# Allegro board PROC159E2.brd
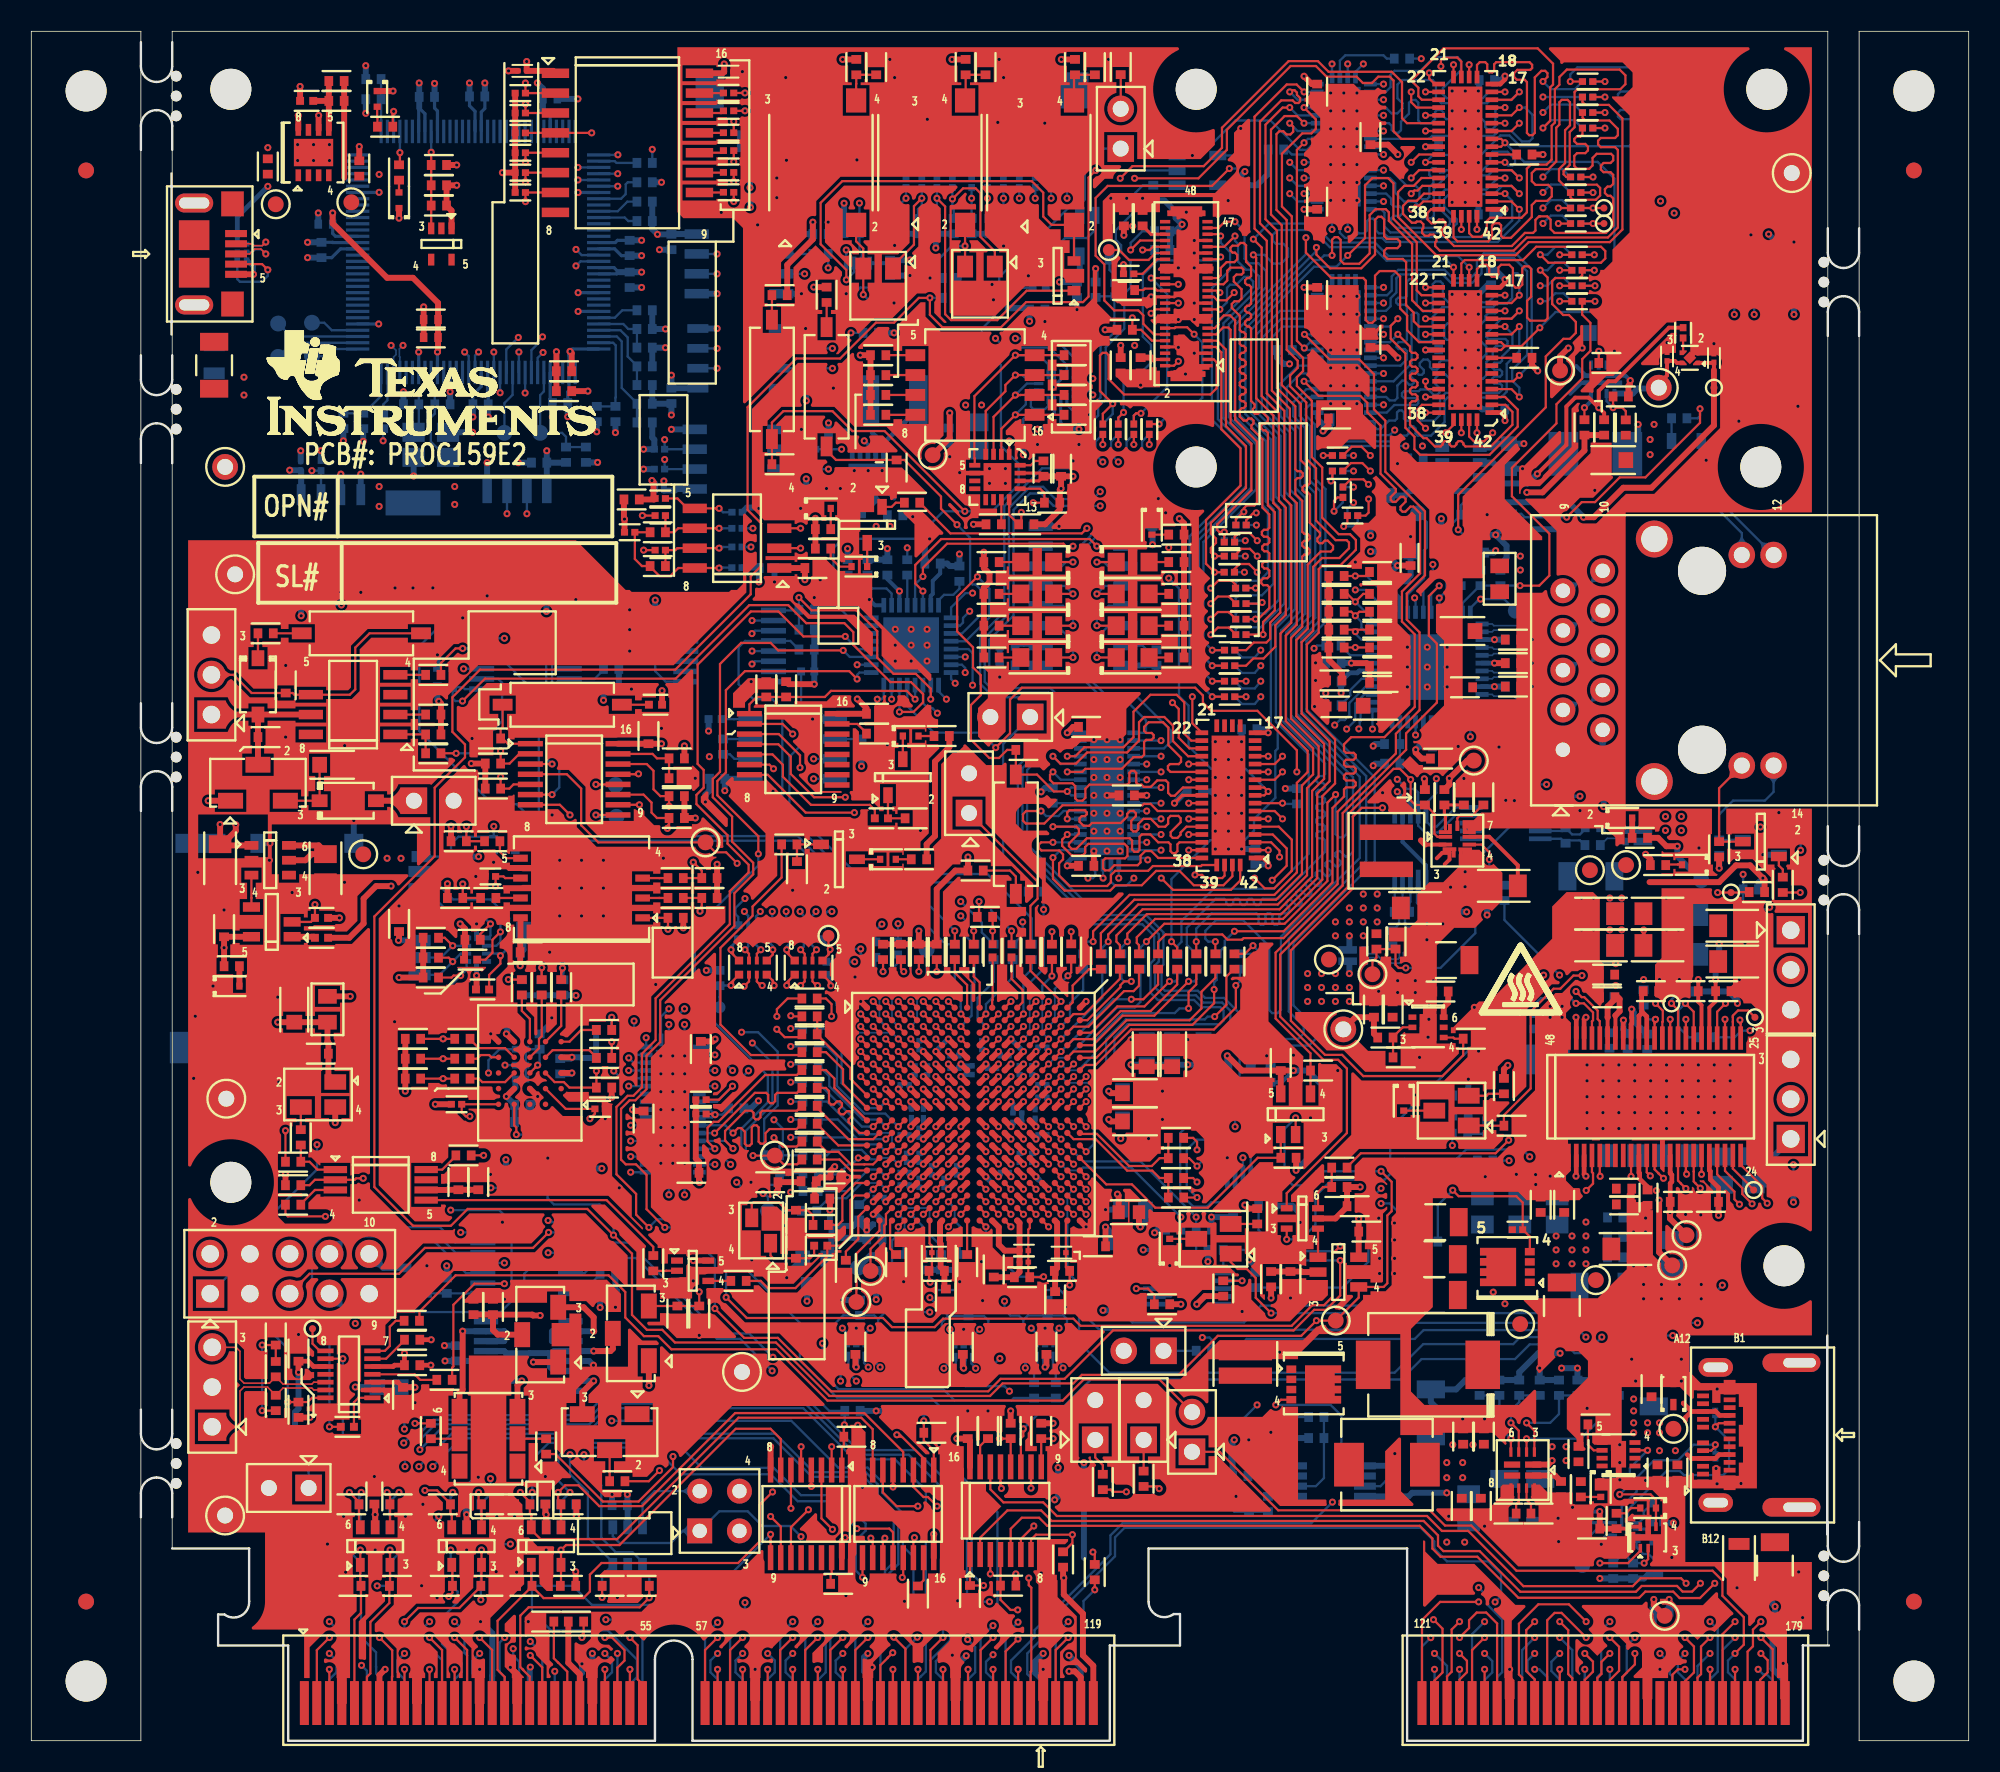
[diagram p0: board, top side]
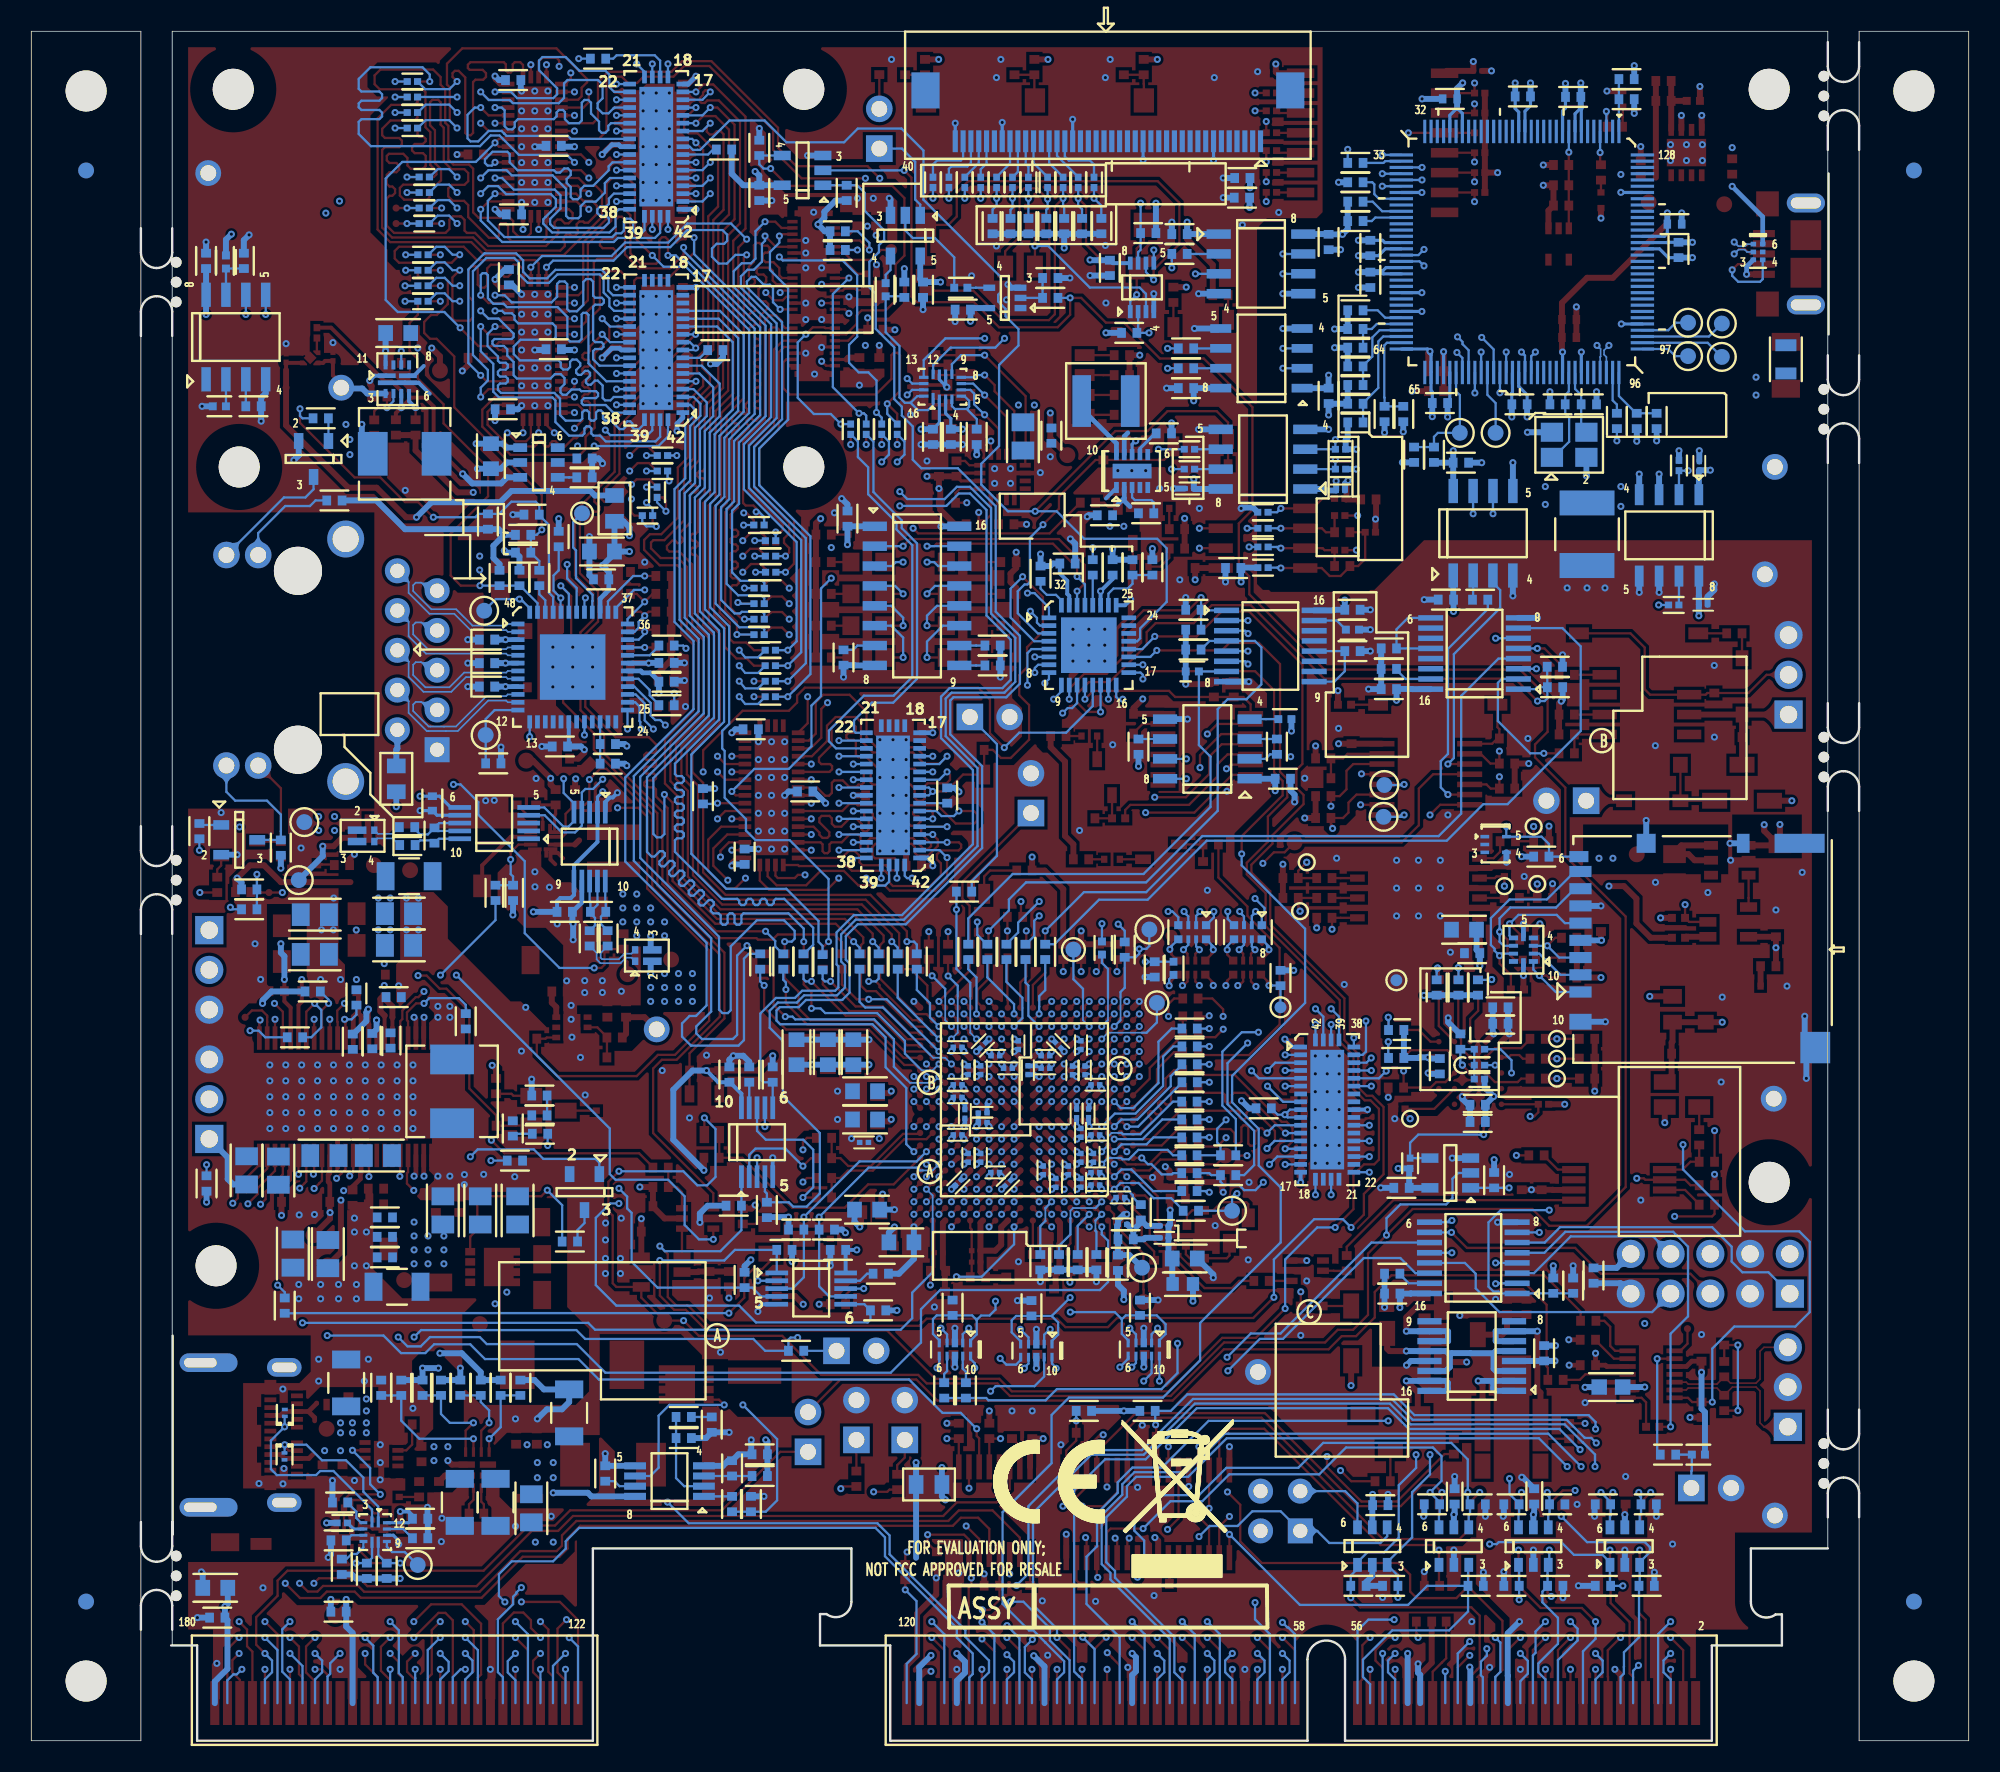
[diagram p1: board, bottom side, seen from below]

Outline 123.76 x 109.21 mm; copper layers: TOP, L02_GND1, L03_SIG1, L04_GND2, L05_PWR1, L06_PWR2, L07_GND3, L08_SIG2, L09_GND4, BOTTOM. Coordinates in mm from the lower left corner of the outline.
Outline path: 0,109.21 0,0 7,0 7,109.21 0,109.21 ; 9,109.21 114.76,109.21 114.76,6.09 113.17,6.09 113.17,0 87.89,0 87.89,12.28 71.37,12.28 71.37,8.88 arc(71.92,7.99) 72.97,8.09 73.38,8.09 73.38,6.08 68.89,6.08 68.89,0 42.24,0 42.24,5.2 arc(41.04,6.4) 39.84,5.2 39.84,0 16.41,0 16.41,6.08 11.93,6.08 11.93,8.06 12.34,8.06 arc(13.38,8.01) 13.91,8.9 13.91,12.28 9,12.28 9,109.21 ; 116.76,109.21 116.76,0 123.76,0 123.76,109.21 116.76,109.21

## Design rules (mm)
net group DIFFPAIR4: nets XDS_USB_D_N XDS_USB_D_P
net group DP1: nets MCAN4_CAN_H MCAN4_CAN_L
net group ICSSM_MI1_TX: nets ICSSM_MII1_TXCLK N35821153
net group ICSSM_MII0/MII1_RXCLK_ON: nets ICSSM_MII0/MII1_RXCLK_ON N34780998
net group ICSSM_MII0/MII1_RXER_ON: nets ICSSM_MII0/MII1_RXER_ON N34780980
net group ICSSM_MII0/MII1_TXCLK_ON: nets ICSSM_MII0/MII1_TXCLK_ON N34780978
net group MMC0_CLK: nets MMC0_CLK MMC0_CLK_R
net group OSPI_CS0: nets OSPI_CS0 SOC_OSPI0_CSN0
net group OSPI_DQ0: nets N35248046 OSPI_DQ0
net group OSPI_DQ1: nets N35244293 OSPI_DQ1
net group OSPI_DQ2: nets N35244332 OSPI_DQ2
net group OSPI_DQ3: nets N35244360 OSPI_DQ3
net group OSPI_DQ4: nets N35244387 OSPI_DQ4
net group OSPI_DQ5: nets N35244414 OSPI_DQ5
net group OSPI_DQ6: nets N35244441 OSPI_DQ6
net group OSPI_DQ7: nets N35244468 OSPI_DQ7
net group QSPI_CS1: nets QSPI_CS1 SOC_OSPI0_CSN1
net group QSPI_D0: nets N35230144 QSPI_D0
net group QSPI_D1: nets N35230147 QSPI_D1
net group QSPI_D2: nets N35252647 QSPI_D2
net group QSPI_D3: nets N35230153 QSPI_D3
net group SOC_OSPI0_CLK: nets N34603356 SOC_OSPI0_CLK
net group SOC_OSPI0_D0: nets N34603287 SOC_OSPI0_D0
net group SOC_OSPI0_D1: nets N34603290 SOC_OSPI0_D1
net group SOC_OSPI0_D2: nets N34603584 SOC_OSPI0_D2
net group SOC_OSPI0_D3: nets N34603591 SOC_OSPI0_D3
net group SOC_OSPI0_D4: nets N34800889 SOC_OSPI0_D4
net group SOC_OSPI0_D5: nets N34800892 SOC_OSPI0_D5
net group SOC_OSPI0_D6: nets N34800895 SOC_OSPI0_D6
net group SOC_OSPI0_D7: nets N34603328 SOC_OSPI0_D7
net group SOC_OSPI0_DQS: nets N35329989 SOC_OSPI0_DQS
net group SOC_OSPI0_LBCLK: nets N35329968 SOC_OSPI0_LBCLK
net group HSEC_ADC: nets ADC_CAL0 ADC_CAL0/ADC_R0_AIN0 ADC_CAL1 ADC_CAL1/ADC_R0_AIN1 ADC_CAL2 ADC_CAL3 ADC_R0_AIN0 ADC_R0_AIN1 ADC_R0_AIN2 ADC_R0_AIN3 ADC_R1_AIN0 ADC_R1_AIN1 ADC_R1_AIN2 ADC_R1_AIN3 HSEC_ADC0_AIN0 HSEC_ADC0_AIN0/DAC_OUT HSEC_ADC0_AIN1 HSEC_ADC0_AIN1/DAC_OUT HSEC_ADC0_AIN2 HSEC_ADC0_AIN3 HSEC_ADC0_AIN4 HSEC_ADC0_AIN5 HSEC_ADC1_AIN0 HSEC_ADC1_AIN1 HSEC_ADC1_AIN2 HSEC_ADC1_AIN3 HSEC_ADC1_AIN4 HSEC_ADC1_AIN5 HSEC_ADC2_AIN0 HSEC_ADC2_AIN1 HSEC_ADC2_AIN2 HSEC_ADC2_AIN3 HSEC_ADC3_AIN0 HSEC_ADC3_AIN1 HSEC_ADC3_AIN2 HSEC_ADC3_AIN3 HSEC_ADC3_AIN4 HSEC_ADC3_AIN5 HSEC_ADC4_AIN0 HSEC_ADC4_AIN1
net group N34755833: nets N34869775
net group OPSI_DQS: nets OSPI_DQS_SOC
net group POWER: nets HSEC_VREF_3V3 VBAT_LIN VBAT_XDS VBUS_DET VCC_1V1 VCC_1V2_N VCC_1V2_P VDD_IO_3V3_N VDD_IO_3V3_P VDDC_1V2_XDS VLIN VMAIN_MON VREG VSYS_MON
net group VMAIN_12V0: nets N35537520

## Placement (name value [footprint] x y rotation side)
C1  0.1uF  [CAP0402_0-75]  98.92 14.18 180 bottom
C2  0.1uF  [CAP0402_0-75]  99.7 13.55 180 top
C3  0.1uF  [CAP0402_0-75]  105.15 17.13 270 top
C4  10uF  [CAP1206_2]  103.65 22.86 90 bottom
C5  0.1uF  [CAP0402_0-75]  103.5 22.47 90 top
C6  1000pF  [CAP1206_1-75]  111.38 11.18 90 top
C7  1uF  [CAP0402_0-75]  98.83 18.31 90 top
C8  1uF  [CAP0402_0-75]  103.88 17.13 270 top
C9  1000pF  [CAP0402_0-75]  99.92 20.21 0 top
C10  10uF  [CAP1206_2]  94.1 15.23 270 bottom
C11  1uF  [CAP0402_0-75]  92.6 15 270 top
C12  0.1uF  [CAP0402_0-75]  97.72 16.07 90 top
C13  10uF  [CAP1206_2]  89.4 20.94 90 bottom
C14  1uF  [CAP0402_0-75]  92.79 19.43 90 top
C15  0.1uF  [CAP0402_0-75]  91.47 19.43 90 top
C16  1uF  [CAP0402_0-75]  96.29 14.51 0 top
C17  47uF  [CAP1206_2]  96.39 15.23 270 bottom
C18  22uF  [CAP0805_1-5]  91.82 14.85 270 bottom
C19  0.1uF  [CAP0402_0-75]  91.38 15 270 top
C20  0.1uF  [CAP0402_0-75]  77.23 18.3 0 bottom
C21  47uF  [CAP1206_2]  89.69 33.13 180 top
C22  4700pF  [CAP0402_0-75]  82.08 19.33 180 bottom
C23  0.1uF  [CAP0402_0-75]  82.08 20.68 180 bottom
C24  10pF  [CAP0402_0-75]  77.79 15.12 90 bottom
C30  1000pF  [CAP0402_0-75]  100.65 48.94 180 top
C31  0.1uF  [CAP0402_0-75]  100.67 47.49 180 top
C32  22uF  [CAP0805_1-5]  100.27 52.84 180 bottom
C33  22uF  [CAP0805_1-5]  100.27 50.81 180 top
C34  22uF  [CAP0805_1-5]  100.27 50.81 180 bottom
C35  22uF  [CAP0805_1-5]  100.27 52.84 180 top
C36  0.1uF  [CAP0402_0-75]  100.61 47.5 180 bottom
C37  0.1uF  [CAP0402_0-75]  100.81 44.73 270 bottom
C38  220uF  [CAP1206_2]  99.63 55.23 180 bottom
C43  220uF  [CAP1206_2]  100.4 29 0 bottom
C44  10uF  [CAP0805_1-5]  97.47 33.88 90 bottom
C45  10uF  [CAP0805_1-5]  101.83 31.41 0 top
C46  10uF  [CAP0805_1-5]  95.08 33.88 90 bottom
C47  10uF  [CAP0805_1-5]  92.7 33.88 90 bottom
C48  2.2uF  [CAP0402_0-75]  97.92 34.24 90 top
C49  2.2uF  [CAP0402_0-75]  101.17 30.88 0 bottom
C50  1000pF  [CAP0402_0-75]  101.17 32.19 0 bottom
C51  1000pF  [CAP0402_0-75]  101.74 34.26 0 top
C52  0.1uF  [CAP0402_0-75]  96.42 34.24 90 top
C53  0.1uF  [CAP0402_0-75]  101.17 33.43 0 bottom
C54  0.1uF  [CAP0402_0-75]  101.74 35.27 0 top
C55  0.1uF  [CAP0402_0-75]  91.26 38.78 180 bottom
C56  0.1uF  [CAP0402_0-75]  96.01 45.96 90 bottom
C57  0.01uF  [CAP0402_0-75]  91.3 41.22 0 bottom
C58  10uF  [CAP0805_1-5]  103.88 52.84 0 top
C59  10uF  [CAP0805_1-5]  103.88 50.81 0 top
C60  0.1uF  [CAP0402_0-75]  103.46 47.89 0 top
C61  2.2uF  [CAP0402_0-75]  103.22 44.66 270 bottom
C62  4.7uF  [CAP0402_0-75]  101.98 44.69 270 bottom
C64  10uF  [CAP0805_1-5]  105.04 37.38 0 bottom
C65  10uF  [CAP0805_1-5]  101.62 37.38 180 bottom
C66  0.1uF  [CAP0402_0-75]  103.24 34.69 270 top
C67  10uF  [CAP0805_1-5]  107.05 31.12 270 bottom
C68  10uF  [CAP0805_1-5]  104.82 31.09 270 bottom
C69  0.1uF  [CAP0402_0-75]  105.18 34.42 0 top
C70  10uF  [CAP0805_1-5]  105.65 52.77 180 bottom
C71  10uF  [CAP0805_1-5]  105.65 50.23 180 bottom
C72  0.1uF  [CAP0402_0-75]  105.99 47.89 180 top
C73  0.1uF  [CAP0402_0-75]  59.82 19.79 90 top
C74  10uF  [CAP0805_1-5]  110.01 36.44 90 bottom
C75  10uF  [CAP0805_1-5]  107.98 36.42 90 bottom
C76  0.1uF  [CAP0402_0-75]  107.29 34.42 180 top
C77  10uF  [CAP0805_1-5]  108.65 49.78 0 top
C78  10uF  [CAP0805_1-5]  108.65 52.06 0 top
C79  0.1uF  [CAP0402_0-75]  108.08 47.89 0 top
C80  10uF  [CAP0805_1-5]  94.06 54.61 180 top
C81  22uF  [CAP0805_1-5]  88.39 53.2 0 top
C82  6800pF  [CAP0402_0-75]  92.76 60.27 90 top
C83  2.2uF  [CAP0402_0-75]  55.18 78.29 0 bottom
C84  22uF  [CAP0805_1-5]  60.42 83.33 270 bottom
C85  0.1uF  [CAP0402_0-75]  58.6 83.37 270 bottom
C86  0.1uF  [CAP0402_0-75]  53.84 65.61 0 top
C89  0.1uF  [CAP0402_0-75]  89.69 52.95 180 bottom
C90  0.1uF  [CAP0402_0-75]  98.14 59.88 270 bottom
C91  0.1uF  [CAP0402_0-75]  87.55 52.95 0 bottom
C92  0.1uF  [CAP0402_0-75]  98.01 57.83 90 bottom
C93  10uF  [CAP0603_1]  100.33 89.93 0 bottom
C94  22uF  [CAP0603_1]  101.05 81.81 180 top
C95  0.01uF  [CAP0402_0-75]  100.62 88.02 0 top
C96  1uF  [CAP0201_0-5]  104.49 88.43 90 top
C97  1uF  [CAP0201_0-5]  107.49 88.34 90 top
C98  10uF  [CAP0603_1]  94.4 82.06 270 bottom
C99  0.01uF  [CAP0402_0-75]  88.42 80.71 180 bottom
C100  1uF  [CAP0402_0-75]  88.42 81.92 180 bottom
C101  0.1uF  [CAP0201_0-5]  51.33 35.98 0 top
C102  3.3uF  [CAP0603_1]  74.88 43.99 90 bottom
C103  3.3uF  [CAP0603_1]  72.88 43.99 90 bottom
C104  3.3uF  [CAP0603_1]  68.18 31.84 180 bottom
C105  0.1uF  [CAP0201_0-5]  64.59 44.31 180 bottom
C106  0.1uF  [CAP0201_0-5]  56.7 44.44 270 bottom
C107  0.1uF  [CAP0201_0-5]  55.79 38.71 0 bottom
C108  0.1uF  [CAP0402_0-75]  68.13 31.59 180 top
C109  0.1uF  [CAP0201_0-5]  54.19 34.71 180 bottom
C110  0.1uF  [CAP0201_0-5]  58.97 43.75 180 bottom
C111  0.1uF  [CAP0201_0-5]  60.1 42.84 270 bottom
C112  0.1uF  [CAP0201_0-5]  64.12 40.04 90 bottom
C113  0.1uF  [CAP0201_0-5]  63.9 37.24 90 bottom
C114  0.1uF  [CAP0201_0-5]  62.99 39.51 180 bottom
C115  0.1uF  [CAP0201_0-5]  63.1 42.84 90 bottom
C116  0.1uF  [CAP0201_0-5]  63.1 37.24 90 bottom
C117  0.1uF  [CAP0201_0-5]  55.9 37.24 90 bottom
C118  0.1uF  [CAP0201_0-5]  60.7 44.44 270 bottom
C119  3.3uF  [CAP0603_1]  71.25 43.99 90 bottom
C120  3.3uF  [CAP0603_1]  71.25 43.86 90 top
C121  3.3uF  [CAP0603_1]  72.88 43.86 90 top
C122  0.1uF  [CAP0201_0-5]  56.99 40.07 90 bottom
C123  0.1uF  [CAP0201_0-5]  62.99 40.11 180 bottom
C124  0.1uF  [CAP0201_0-5]  64.59 41.11 180 bottom
C125  0.1uF  [CAP0201_0-5]  57.26 42.82 90 bottom
C126  0.1uF  [CAP0201_0-5]  58.97 42.95 180 bottom
C127  0.1uF  [CAP0201_0-5]  62.17 43.75 0 bottom
C128  0.1uF  [CAP0201_0-5]  56.46 42.82 90 bottom
C129  0.1uF  [CAP0201_0-5]  56.22 40.08 90 bottom
C130  0.1uF  [CAP0201_0-5]  56.7 37.24 90 bottom
C131  0.1uF  [CAP0201_0-5]  56.7 38.84 270 bottom
C132  0.1uF  [CAP0201_0-5]  63.9 42.84 90 bottom
C133  0.1uF  [CAP0201_0-5]  61.37 42.95 180 bottom
C134  3.3uF  [CAP0603_1]  70.37 33.93 180 bottom
C135  0.1uF  [CAP0201_0-5]  59.1 36.44 90 bottom
C136  0.1uF  [CAP0201_0-5]  62.19 36.31 0 bottom
C137  0.1uF  [CAP0201_0-5]  57.5 36.44 90 bottom
C138  3.3uF  [CAP0603_1]  70.5 39.69 0 bottom
C139  0.1uF  [CAP0201_0-5]  64.54 35.66 135 bottom
C140  4.7uF  [CAP0603_1]  50.08 30.8 180 bottom
C141  0.1uF  [CAP0201_0-5]  51.39 32.13 0 bottom
C142  0.1uF  [CAP0201_0-5]  51.39 32.89 0 bottom
C143  0.1uF  [CAP0201_0-5]  56.7 35.64 90 bottom
C144  0.1uF  [CAP0201_0-5]  61.38 35.62 135 bottom
C145  0.1uF  [CAP0201_0-5]  58.3 35.64 90 bottom
C146  0.1uF  [CAP0201_0-5]  55.79 35.51 0 bottom
C147  3.3uF  [CAP0603_1]  70.5 41.49 0 bottom
C148  3.3uF  [CAP0603_1]  70.5 41.37 0 top
C149  3.3uF  [CAP0603_1]  70.5 39.56 0 top
C150  0.1uF  [CAP0201_0-5]  55.79 36.31 0 bottom
C151  0.1uF  [CAP0201_0-5]  70.56 38.22 0 bottom
C152  0.1uF  [CAP0201_0-5]  58.17 44.43 225 bottom
C153  0.1uF  [CAP0201_0-5]  64.59 38.71 180 bottom
C154  0.1uF  [CAP0201_0-5]  55.79 41.91 0 bottom
C155  0.1uF  [CAP0201_0-5]  64.59 41.91 180 bottom
C156  0.1uF  [CAP0201_0-5]  62.98 44.42 315 bottom
C157  0.1uF  [CAP0402_0-75]  31.72 50.37 0 top
C158  0.1uF  [CAP0402_0-75]  31.72 50.31 0 bottom
C159  4.7uF  [CAP0603_1]  32.24 51.81 180 bottom
C160  0.1uF  [CAP0402_0-75]  29.92 46.85 180 bottom
C161  0.1uF  [CAP0402_0-75]  33.78 43.09 270 bottom
C162  0.1uF  [CAP0402_0-75]  31.36 40.63 0 bottom
C163  0.1uF  [CAP0402_0-75]  29.92 45.8 180 bottom
C164  4.7uF  [CAP0402_0-75]  31.36 39.53 180 bottom
C166  0.1uF  [CAP0402_0-75]  36.23 35.32 0 bottom
C167  0.1uF  [CAP0402_0-75]  12.31 51.85 90 top
C168  22uF  [CAP0805_1-5]  12.06 56.38 270 top
C169  22uF  [CAP0805_1-5]  18.79 55.74 270 top
C170  0.1uF  [CAP0402_0-75]  23.49 52.18 90 top
C171  0.1uF  [CAP0402_0-75]  39.37 72.25 180 bottom
C172  0.1uF  [CAP0402_0-75]  43.81 61.46 0 bottom
C173  0.1uF  [CAP0402_0-75]  112.6 94.54 90 bottom
C174  0.1uF  [CAP0402_0-75]  23.74 22.09 90 top
C175  0.1uF  [CAP0402_0-75]  24.33 23.99 180 top
C176  4700pF  [CAP0402_0-75]  15.62 25.77 90 top
C177  0.1uF  [CAP0402_0-75]  39.42 64.18 90 top
C178  1uF  [CAP0402_0-75]  41.23 62.76 180 top
C179  0.1uF  [CAP0402_0-75]  33.4 72.9 180 bottom
C180  0.1uF  [CAP0402_0-75]  32.44 81.65 0 bottom
C181  0.1uF  [CAP0402_0-75]  50 86.41 180 bottom
C182  0.1uF  [CAP0402_0-75]  40.89 85.92 90 bottom
C183  10pF  [CAP1812_1-25]  24.38 77.08 90 bottom
C184  12pF  [CAP0402_0-75]  48.85 31.31 90 top
C185  12pF  [CAP0402_0-75]  48.85 33.4 270 top
C186  22pF  [CAP0201_0-5]  54.06 32.98 0 bottom
C187  0.1uF  [CAP0402_0-75]  23.97 29.72 90 bottom
C188  0.1uF  [CAP0402_0-75]  36.83 28.56 0 bottom
C189  0.1uF  [CAP0402_0-75]  79.81 43.3 90 top
C190  10uF  [CAP0603_1]  87.31 75.97 0 bottom
C191  1uF  [CAP0402_0-75]  85.97 67.59 0 top
C192  1uF  [CAP0402_0-75]  85.97 68.66 0 top
C193  1uF  [CAP0402_0-75]  83.18 68.86 180 bottom
C195  0.1uF  [CAP0402_0-75]  94.65 68.84 0 top
C196  0.1uF  [CAP0402_0-75]  87.36 74.19 0 bottom
C197  0.1uF  [CAP0402_0-75]  88.11 75.57 90 top
C199  0.01uF  [CAP0402_0-75]  94.65 68.84 0 bottom
C206  10uF  [CAP0603_1]  91.42 70.89 180 top
C207  1uF  [CAP0402_0-75]  94.65 67.34 0 bottom
C208  1uF  [CAP0402_0-75]  94.65 70.34 0 bottom
C209  0.1uF  [CAP0402_0-75]  94.65 67.34 0 top
C210  0.1uF  [CAP0402_0-75]  91.58 67.3 180 top
C211  0.01uF  [CAP0402_0-75]  94.65 70.34 0 top
C212  10uF  [CAP0603_1]  85.88 66.12 0 top
C213  1uF  [CAP0402_0-75]  83.27 66.07 180 top
C214  1uF  [CAP0402_0-75]  83.18 67.65 180 bottom
C216  0.1uF  [CAP0402_0-75]  90 63.52 0 bottom
C217  0.1uF  [CAP0402_0-75]  89.87 62.74 0 top
C219  0.01uF  [CAP0402_0-75]  83.24 67.74 180 top
C220  10uF  [CAP0402_0-75]  69.59 87.87 270 top
C221  0.1uF  [CAP0402_0-75]  70.86 87.87 270 top
C222  0.1uF  [CAP0402_0-75]  77.26 98.88 270 bottom
C225  10uF  [CAP0402_0-75]  70.99 97.27 90 top
C226  0.1uF  [CAP0402_0-75]  69.79 97.27 90 top
C230  10uF  [CAP0603_1]  16.8 46.7 90 top
C231  1uF  [CAP0402_0-75]  28.55 35.69 90 top
C232  0.1uF  [CAP0402_0-75]  27.28 35.69 90 top
C233  0.01uF  [CAP0402_0-75]  18.49 43.89 180 top
C234  0.1uF  [CAP0402_0-75]  37.04 67.18 0 bottom
C235  10uF  [CAP0603_1]  19.22 62.35 0 top
C236  0.1uF  [CAP0402_0-75]  14.97 64.12 0 top
C237  220pF  [CAP0402_0-75]  16.25 67.42 90 top
C238  0.1uF  [CAP0402_0-75]  46.43 98.58 0 bottom
C239  0.1uF  [CAP0402_0-75]  46.4 99.83 0 bottom
C240  0.1uF  [CAP0402_0-75]  49.91 74.92 0 top
C241  0.1uF  [CAP0402_0-75]  46.99 74.92 0 bottom
C242  0.1uF  [CAP0402_0-75]  65.02 83.3 270 bottom
C243  0.1uF  [CAP0402_0-75]  66.16 83.3 270 bottom
C244  0.1uF  [CAP0402_0-75]  65.78 81.27 90 top
C245  0.1uF  [CAP0402_0-75]  64.26 91.43 180 bottom
C246  0.1uF  [CAP0402_0-75]  66.8 92.7 90 bottom
C247  1000pF  [CAP0402_0-75]  58.67 93.45 180 bottom
C248  15pF  [CAP0402_0-75]  19.49 106.03 180 top
C249  1uF  [CAP0402_0-75]  20.95 100.44 90 top
C250  1uF  [CAP0402_0-75]  28.48 105.04 0 bottom
C251  0.1uF  [CAP0402_0-75]  25.27 105.02 0 bottom
C252  0.1uF  [CAP0402_0-75]  28.7 85.37 180 bottom
C253  0.01uF  [CAP0402_0-75]  38.22 95.36 270 bottom
C254  0.01uF  [CAP0402_0-75]  18.54 95.24 90 bottom
C255  0.01uF  [CAP0402_0-75]  33.78 85.46 0 bottom
C256  2.2uF  [CAP0402_0-75]  15.11 100.57 90 top
C257  1uF  [CAP0402_0-75]  38.22 93.33 270 bottom
C258  0.01uF  [CAP0402_0-75]  33.14 104.89 0 bottom
C259  2.2uF  [CAP0402_0-75]  25.52 89.65 180 top
C260  1uF  [CAP0402_0-75]  25.52 90.79 180 top
C261  0.01uF  [CAP0402_0-75]  18.79 96.89 180 bottom
C262  0.1uF  [CAP0402_0-75]  34.03 87.49 0 top
C263  1000pF  [CAP1206_1-75]  11.68 87.87 270 top
C264  0.1uF  [CAP0402_0-75]  21.2 84.32 270 bottom
C265  0.1uF  [CAP0402_0-75]  50.41 96.25 0 bottom
C266  0.1uF  [CAP0402_0-75]  40.89 95.75 270 bottom
C267  0.01uF  [CAP0402_0-75]  26.03 98.07 0 top
C268  0.1uF  [CAP0402_0-75]  26.03 99.37 0 top
C269  12pF  [CAP0402_0-75]  26.26 85.37 180 bottom
C270  12pF  [CAP0402_0-75]  24.26 85.37 0 bottom
C271  0.1uF  [CAP0201_0-5]  40.13 79.87 0 bottom
C272  0.1uF  [CAP0201_0-5]  49.78 80 180 bottom
C273  0.1uF  [CAP0201_0-5]  31.36 106.68 0 top
C274  0.1uF  [CAP0201_0-5]  17.21 81.45 90 bottom
C275  0.1uF  [CAP0201_0-5]  16.96 72.57 180 bottom
C276  0.1uF  [CAP0402_0-75]  71.62 78.07 90 bottom
C277  0.1uF  [CAP0402_0-75]  57.57 75.21 180 bottom
C278  0.1uF  [CAP0402_0-75]  54.69 74.96 90 bottom
C279  0.1uF  [CAP0402_0-75]  29.49 27.71 90 top
C280  4.7uF  [CAP0402_0-75]  28.25 27.71 90 top
C281  0.1uF  [CAP0402_0-75]  37.59 15.05 180 bottom
C282  0.1uF  [CAP0402_0-75]  27.76 15.61 90 bottom
C283  0.1uF  [CAP0402_0-75]  32.84 15.61 90 bottom
C284  0.1uF  [CAP0402_0-75]  27.12 24.75 90 bottom
C285  4.7uF  [CAP0402_0-75]  63.29 29.61 180 top
C286  0.1uF  [CAP0201_0-5]  63.41 30.58 180 top
C287  0.1uF  [CAP0201_0-5]  63.41 31.31 180 top
C288  4.7uF  [CAP0402_0-75]  57.84 30.01 0 top
C289  0.1uF  [CAP0201_0-5]  57.81 31.18 0 top
C290  330pF  [CAP0402_0-75]  20.57 9.89 180 top
C291  330pF  [CAP0402_0-75]  23.36 9.89 0 top
C292  330pF  [CAP0402_0-75]  23.36 15.1 0 bottom
C293  330pF  [CAP0402_0-75]  20.44 15.1 180 bottom
C294  330pF  [CAP0402_0-75]  26.28 15.1 180 top
C295  330pF  [CAP0402_0-75]  29.25 15.1 0 top
C296  330pF  [CAP0402_0-75]  23.36 9.89 0 bottom
C297  330pF  [CAP0402_0-75]  20.57 9.89 180 bottom
C298  330pF  [CAP0402_0-75]  26.41 9.89 180 top
C299  330pF  [CAP0402_0-75]  29.21 9.89 0 top
C300  330pF  [CAP0402_0-75]  29.21 15.1 0 bottom
C301  330pF  [CAP0402_0-75]  26.28 15.1 180 bottom
C302  330pF  [CAP0402_0-75]  29.21 9.89 0 bottom
C303  330pF  [CAP0402_0-75]  26.41 9.89 180 bottom
C304  330pF  [CAP0402_0-75]  38.98 9.89 180 top
C305  330pF  [CAP0402_0-75]  36.95 9.89 0 top
C306  330pF  [CAP0402_0-75]  23.41 15.1 0 top
C307  330pF  [CAP0402_0-75]  20.44 15.1 180 top
C308  330pF  [CAP0402_0-75]  38.98 9.89 180 bottom
C309  330pF  [CAP0402_0-75]  36.95 9.89 0 bottom
C314  0.1uF  [CAP0402_0-75]  21.92 15.61 90 top
C315  0.1uF  [CAP0402_0-75]  32.84 15.61 90 top
C316  0.1uF  [CAP0402_0-75]  59.5 25.17 270 top
C318  330pF  [CAP0402_0-75]  31.49 9.89 180 bottom
C319  330pF  [CAP0402_0-75]  34.29 15.1 0 bottom
C320  330pF  [CAP0402_0-75]  31.36 15.1 180 bottom
C321  330pF  [CAP0402_0-75]  31.49 9.89 180 top
C322  330pF  [CAP0402_0-75]  34.29 9.89 0 top
C323  330pF  [CAP0402_0-75]  31.36 15.1 180 top
C324  330pF  [CAP0402_0-75]  34.33 15.1 0 top
C329  0.1uF  [CAP0402_0-75]  64.85 25.17 90 top
C330  0.1uF  [CAP0402_0-75]  52.64 25.17 270 top
C331  0.1uF  [CAP0402_0-75]  41.27 27.28 270 top
C332  10uF  [CAP0603_1]  112.01 9.77 0 bottom
C333  0.1uF  [CAP0402_0-75]  111.88 7.86 0 bottom
C334  0.1uF  [CAP0402_0-75]  104.14 8.24 0 bottom
C335  0.1uF  [CAP0402_0-75]  54.86 94.09 270 bottom
C336  0.1uF  [CAP0402_0-75]  53.97 106.92 90 top
C337  0.1uF  [CAP0402_0-75]  60.96 106.92 90 top
C338  0.1uF  [CAP0402_0-75]  67.94 106.92 90 top
C340  0.1uF  [CAP0402_0-75]  84.54 34.15 0 top
C341  0.1uF  [CAP0402_0-75]  85.28 32.52 0 top
C344  10uF  [CAP1206_2]  90.37 49.87 180 top
C345  0.1uF  [CAP0402_0-75]  90.02 47.86 180 top
C346  2.2uF  [CAP0402_0-75]  85.77 46.71 90 top
C347  0.1uF  [CAP0402_0-75]  86.96 46.71 90 top
C348  0.1uF  [CAP0402_0-75]  17.07 24.74 270 top
C349  4.7uF  [CAP0402_0-75]  65.84 30.01 180 top
C350  0.1uF  [CAP0201_0-5]  65.81 31.18 180 top
C351  0.1uF  [CAP0201_0-5]  44.54 106.63 180 top
C352  0.1uF  [CAP0402_0-75]  38.35 79.3 0 top
C353  47uF  [CAP1206_2]  89.63 28.47 180 top
C354  47uF  [CAP1206_2]  89.63 30.76 180 top
C355  47uF  [CAP1206_2]  97.77 27.77 270 top
C356  0.1uF  [CAP0402_0-75]  72.23 31.36 0 bottom
C357  0.1uF  [CAP0402_0-75]  78.19 56.47 90 bottom
C358  0.1uF  [CAP0402_0-75]  77.8 64.62 180 bottom
C359  0.1uF  [CAP0402_0-75]  74.33 60.64 0 bottom
C360  0.1uF  [CAP0402_0-75]  67.39 55.89 0 top
C361  0.1uF  [CAP0402_0-75]  67.39 64.77 0 top
C362  0.1uF  [CAP0402_0-75]  69.98 60.39 180 top
C363  0.1uF  [CAP0402_0-75]  92.93 97.51 180 bottom
C364  0.1uF  [CAP0402_0-75]  92.98 106.09 180 bottom
C365  0.1uF  [CAP0402_0-75]  90.39 101.89 0 bottom
C366  0.1uF  [CAP0402_0-75]  93.64 85.06 180 bottom
C367  0.1uF  [CAP0402_0-75]  93.25 93.5 270 bottom
C368  0.1uF  [CAP0402_0-75]  90.39 88.9 0 bottom
C369  0.1uF  [CAP0402_0-75]  83.35 84.47 0 top
C370  0.1uF  [CAP0402_0-75]  82.14 92.36 270 top
C371  0.1uF  [CAP0402_0-75]  85.54 89.5 90 top
C372  0.1uF  [CAP0402_0-75]  82.14 98.33 90 top
C373  0.1uF  [CAP0402_0-75]  82.14 105.35 270 top
C374  0.1uF  [CAP0402_0-75]  85.54 102.45 90 top
C3743  0.1uF  [CAP0402_0-75]  42.16 36.28 180 top
C3744  0.1uF  [CAP0402_0-75]  42.77 44.19 270 top
C3745  0.1uF  [CAP0402_0-75]  39.11 39.74 270 top
C3746  0.1uF  [CAP0402_0-75]  79.17 42.56 90 bottom
D1  TPD1E01B04DPLT  [DIO_DFN0201_0-4]  107.58 18.16 270 bottom
D2  TPD1E01B04DPLT  [DIO_DFN0201_0-4]  107.56 20.94 90 bottom
D3  PESD5Z6.0  [DIO_SOD523F_0-7]  104.9 22.21 90 top
D4  B540C-13-F  [DIO_SMC]  89.21 24.02 180 top
D6  1N4148W-7-F  [DIO_SOD123_1-4]  14.48 67.36 270 top
D7  1N4148W-7-F  [DIO_SOD123_1-4]  20.22 60.05 0 top
FB1  120E  [EMIFIL_BLM18S_0603_0-7]  22.86 22.59 0 bottom
FL1  120E  [EMIFIL_BLM18R_0603_1]  70.11 33.76 0 top
FL2  120E  [EMIFIL_BLM18R_0603_1]  50.2 29.18 180 bottom
FL3  100E  [EMIFIL_BLM18R_0603]  100.44 61.45 90 bottom
FL4  100E  [EMIFIL_BLM18R_0603]  86.51 78.73 270 bottom
FL5  100E  [EMIFIL_BLM18R_0603]  93.8 74.23 270 top
FL6  100E  [EMIFIL_BLM18R_0603]  18.92 46.73 90 top
FL7  100E  [EMIFIL_BLM18R_0603]  66.42 16.37 180 bottom
J1  CON_USB-C_24_F  [CON_USBC24_2012670_S_R_S_3-9]  110.85 19.53 90 top
J2  HDR_1X3  [HDR_1X3_100_S_T]  112.39 51.78 90 top
J3  HDR_1X3  [HDR_1X3_100_S_T]  112.39 38.44 270 top
J4  CON_SDCARD10_DM3BT-DSF-PEJS  [CON_SD10_DM3BT-DSF-PEJS_S_R_S_2-4]  17 50.55 90 bottom
J5  HDR_1X3  [HDR_1X3_100_S_T]  11.55 20.05 270 top
J6  HDR_2X5  [HDR_2X5_61301021121_S_T_8-6]  11.43 28.56 0 top
J7  CON_RJ45-14_LPJG16314A4NL  [CON_RJ45-14_LPJG16314A4NL_S_R_T_13-6]  97.84 63.31 90 top
J8  CON_BTOB_2X24_M  [CON_BTOB2X24_DF40GB-48DP_P_S_S_1-3]  73.78 92.44 90 top
J9  HDR_2X1  [HDR_2X1_100_S_T]  24.44 60.05 180 top
J10  HDR_1X3  [HDR_1X3_100_S_T]  11.51 65.56 270 top
J11  CON_FLEX_40X1_FH12A-40S-0.5SH  [CON_FLEX40X1_FH12A_S_R_S]  54.99 105.76 0 bottom
J12  HDR_2X1  [HDR_2X1_100_S_T]  69.59 101.71 270 top
J13  CON_MUSB-B_5_F  [CON_USBB5_2013499-1_S_R_S_3]  10.57 94.98 270 top
J14  HDR_2X2  [HDR_2X2_5-146256-2_S_T_8-3]  42.7 13.4 0 top
J15  CON_EDGE_PCIE_180_M  [CON_EDGE180_HSEC8-180_FING_P_R_S]  64.74 2.4 0 top
J16  HDR_2X1  [HDR_2X1_100_S_T_10-8]  71.05 19.22 270 top
J17  HDR_2X1  [HDR_2X1_100_S_T_10-8]  63.81 65.4 0 top
J18  HDR_2X1  [HDR_2X1_100_S_T_10-8]  59.9 59.26 270 top
J19  HDR_2X1  [HDR_2X1_100_S_T_10-8]  67.96 19.22 270 top
J20  HDR_2X1  [HDR_2X1_100_S_T_10-8]  72.32 24.91 0 top
J21  HDR_2X1  [HDR_2X1_100_S_T_10-8]  17.71 16.15 0 top
J22  HDR_2X1  [HDR_2X1_100_S_T_10-8]  74.14 18.46 270 top
L1  4.7uH  [IND_IHLP2020CZ-01_210X210_SMD_3]  86.6 17.63 180 top
L3  2.2uH  [IND_IHLP2020B_230X215_SMD]  96.88 41.49 90 bottom
L4  1uH  [IND_XAL4020_170X170_SMD_3-1]  86.56 56.85 270 top
L5  10uH  [IND_74405042100_170X170_SMD_2]  55.11 85.59 0 bottom
L6  1uH  [IND_IHLP2020B_230X215_SMD]  99.91 82.21 0 bottom
LD1  150040RS73220  [LED_150040GS73220_40X20_SMD_0-4]  103.28 14.86 180 top
LD2  150040VS73220  [LED_150040GS73220_40X20_SMD_0-4]  100.26 16.07 270 top
LD3  150040VS73220  [LED_150040GS73220_40X20_SMD_0-4]  105.94 55.96 180 top
LD4  150040VS73220  [LED_150040GS73220_40X20_SMD_0-4]  52.9 75.01 180 top
LD5  150040VS73220  [LED_150040GS73220_40X20_SMD_0-4]  50.57 78.73 0 top
LD6  150040RS73220  [LED_150040GS73220_40X20_SMD_0-4]  56.17 64.19 0 top
LD7  150040VS73220  [LED_150040GS73220_40X20_SMD_0-4]  54.72 56.31 0 top
LD8  150040RS73220  [LED_150040GS73220_40X20_SMD_0-4]  87.67 40.75 270 top
LD9  150040VS73220  [LED_150040GS73220_40X20_SMD_0-4]  23.49 98.41 90 top
LD10  150040RS73220  [LED_150040GS73220_40X20_SMD_0-4]  22.09 104.89 270 top
LD11  150080VS75000  [LED_150080VS75000_80X50_SMD_0-8]  70.35 75.3 0 top
LD12  150080VS75000  [LED_150080VS75000_80X50_SMD_0-8]  70.35 73.27 0 top
LD13  150080VS75000  [LED_150080VS75000_80X50_SMD_0-8]  70.35 71.23 0 top
LD14  150080VS75000  [LED_150080VS75000_80X50_SMD_0-8]  70.35 69.2 0 top
LD15  150080VS75000  [LED_150080VS75000_80X50_SMD_0-8]  64.26 69.2 180 top
LD16  150080VS75000  [LED_150080VS75000_80X50_SMD_0-8]  64.26 71.23 180 top
LD17  150080VS75000  [LED_150080VS75000_80X50_SMD_0-8]  64.26 73.27 180 top
LD18  150080VS75000  [LED_150080VS75000_80X50_SMD_0-8]  64.26 75.3 180 top
LD19  150040RS73220  [LED_150040GS73220_40X20_SMD_0-4]  72.72 31.56 90 top
LD20  150040VS73220  [LED_150040GS73220_40X20_SMD_0-4]  101.76 58.95 0 top
LD21  150040VS73220  [LED_150040GS73220_40X20_SMD_0-4]  71.58 77.55 270 top
LD22  150040VS73220  [LED_150040GS73220_40X20_SMD_0-4]  12.79 48.21 0 top
NOREF  -  [unnamed]  8 17.71 270 top
NOREF#2  -  [unnamed#2]  3.5 105.4 270 top
NOREF#3  -  [unnamed#2]  74.41 81.37 90 top
NOREF#4  -  [unnamed#2]  12.75 35.67 0 top
NOREF#5  -  [unnamed]  8 105.07 270 top
NOREF#6  -  [#3]  -299.48 162.29 0 top
NOREF#7  -  [#3]  123.76 0 90 top
NOREF#8  -  [#3]  9 12.28 0 top
NOREF#9  -  [unnamed#2]  120.26 3.81 90 top
NOREF#10  -  [unnamed#2]  3.5 8.89 270 top
NOREF#11  -  [unnamed]  115.76 54.98 90 top
NOREF#12  -  [unnamed#2]  12.75 105.5 0 top
NOREF#13  -  [unnamed#2]  110.48 81.37 90 top
NOREF#14  -  [unnamed#2]  120.26 100.32 90 top
NOREF#15  -  [unnamed]  8 62.84 270 top
NOREF#16  -  [unnamed#2]  3.5 100.32 270 top
NOREF#17  -  [unnamed]  8 85.07 270 top
NOREF#18  -  [unnamed#2]  120.26 8.89 90 top
NOREF#19  -  [unnamed#2]  74.41 105.5 90 top
NOREF#20  -  [unnamed]  115.76 10.53 90 top
NOREF#21  -  [#3]  28.14 -22.95 0 top
NOREF#22  -  [#3]  0 0 0 top
NOREF#23  -  [#3]  -265.05 -180.61 0 top
NOREF#24  -  [unnamed]  115.76 93.18 90 top
NOREF#25  -  [unnamed#2]  120.26 105.4 90 top
NOREF#26  -  [#3]  17.6 -117.69 0 top
NOREF#27  -  [unnamed#2]  3.5 3.81 270 top
NOREF#28  -  [#3]  -336.75 -31.84 0 top
NOREF#29  -  [unnamed#2]  110.86 105.5 90 top
NOREF#30  -  [#3]  0 109.21 0 top
NOREF#31  -  [unnamed#2]  111.96 30.34 0 top
NOREF#32  -  [unnamed#2]  120.26 8.89 270 bottom
NOREF#33  -  [unnamed#2]  3.5 8.89 90 bottom
NOREF#34  -  [unnamed#2]  3.5 100.32 90 bottom
NOREF#35  -  [unnamed#2]  120.26 100.32 270 bottom
Q2  BSS138LT1G  [SOT23-123_1-2]  53.4 77.68 270 top
Q3  BSS138LT1G  [SOT23-123_1-2]  55.67 61.56 90 top
Q4  BSS138LT1G  [SOT23-123_1-2]  51.59 56.31 0 top
Q5  IRLML6401  [TO_SOT23-123]  90.72 40.25 90 top
Q6  BSS138LT1G  [SOT23-123_1-2]  105.73 81.88 270 bottom
Q7  BSS138LT1G  [SOT23-123_1-2]  110.48 57.44 180 top
Q8  BSS138LT1G  [SOT23-123_1-2]  110.48 57.55 180 bottom
Q9  IRLML6401  [TO_SOT23-123]  54.1 92.95 180 top
Q10  IRLML6401  [TO_SOT23-123]  60.6 93.08 180 top
Q11  IRLML6401  [TO_SOT23-123#2]  65.56 93.59 180 top
Q12  BSS138LT1G  [SOT23-123_1-2]  88.42 35.05 270 bottom
Q13  CSD25404Q3T  [VSON8_CSD173_130X130_1-1]  94.29 30.26 180 top
Q20  IRLML6401  [TO_SOT23-123]  75.52 32.06 90 top
R1  620E_1%  [RES0402_0-5]  101.27 14.04 90 top
R2  4.7K  [RES0402_0-5]  104.03 15.22 180 bottom
R3  4.7K_1%  [RES0402_0-5]  101.05 10.86 90 bottom
R4  4.7K_1%  [RES0402_0-5]  102.32 10.86 90 bottom
R5  909K_1%  [RES0201_0-5]  103.89 13.91 0 bottom
R6  200K_1%  [RES0402_0-5]  103.92 11.11 90 bottom
R7  10K  [RES0402_0-5]  104.13 12.8 0 bottom
R8  0E  [RES0402_0-5]  98.92 12.93 180 bottom
R9  0E  [RES0805_0-75]  109.09 11.67 90 top
R10  22.1K_1%  [RES0402_0-5]  100.13 22.55 270 bottom
R11  9.53K_1%  [RES0402_0-5]  98.77 22.55 270 bottom
R12  22.1K_1%  [RES0402_0-5]  95.05 22.55 270 bottom
R13  4.7K_1%  [RES0402_0-5]  93.78 22.55 270 bottom
R14  4.7K_1%  [RES0402_0-5]  101.41 22.55 90 bottom
R15  4.7K_1%  [RES0402_0-5]  97.59 22.55 90 bottom
R16  4.7K_1%  [RES0402_0-5]  96.36 22.55 90 bottom
R17  4.7K_1%  [RES0402_0-5]  92.52 22.55 90 bottom
R18  44.2K_1%  [RES0402_0-5]  94.36 14.51 180 top
R20  10K  [RES0201_0-5]  94.94 32.65 180 top
R21  8.45K_1%  [RES0402_0-5]  77.23 16.91 180 bottom
R22  100E_1%  [RES0402_0-5]  79 15.12 270 bottom
R23  26.1K_1%  [RES0402_0-5]  87.1 17.07 90 bottom
R24  1.58K_1%  [RES0402_0-5]  80.29 20.19 270 bottom
R26  1K_1%  [RES0402_0-5]  79 17.4 270 bottom
R27  0.007E_1%  [RES1206_W_0-75]  77.55 24.07 90 top
R28  0E  [RES0402_0-5]  93 39.11 90 bottom
R29  1K_1%  [RES0402_0-5]  91.3 39.95 180 bottom
R31  10K  [RES0402_0-5]  19.21 18.28 0 bottom
R32  0E  [RES0402_0-5]  106.92 44.94 180 bottom
R34  10K  [RES0402_0-5]  74.91 24.91 0 bottom
R36  0E  [RES0402_0-5]  112.57 35.6 270 bottom
R38  10K  [RES0402_0-5]  109.84 54.39 180 bottom
R39  10K  [RES0402_0-5]  102.99 47.49 270 bottom
R40  10K  [RES0402_0-5]  110.23 54.22 180 top
R41  10K  [RES0402_0-5]  105.79 47.87 180 bottom
R42  0E  [RES0402_0-5]  92.87 37.06 180 bottom
R43  10K  [RES0402_0-5]  62.4 9.91 180 top
R44  10K  [RES0402_0-5]  65.91 11.58 90 top
R45  10K  [RES0402_0-5]  64.51 19.79 270 top
R46  10K  [RES0402_0-5]  62.56 19.79 270 top
R47  1K_1%  [RES0402_0-5]  98.99 16.06 270 top
R48  220E  [RES0402_0-5]  103.92 55.94 0 top
R49  10K  [RES0402_0-5]  59.96 9.43 270 top
R50  10K  [RES0402_0-5]  61.11 19.79 90 top
R51  0E  [RES0402_0-5]  94.11 54.17 90 bottom
R52  100K  [RES0402_0-5]  90.27 60.27 270 top
R53  10K_1%  [RES0402_0-5]  85.93 51.07 270 top
R55  10K_1%  [RES0402_0-5]  87.15 51.07 270 top
R56  100K  [RES0402_0-5]  91.51 60.27 270 top
R57  0E  [RES0402_0-5]  52.55 78.42 180 bottom
R58  100K_1%  [RES0402_0-5]  51.41 83.52 180 bottom
R59  10K_1%  [RES0402_0-5]  89.02 60.27 270 top
R62  10K  [RES0402_0-5]  48.22 67.17 270 top
R63  0E  [RES0402_0-5]  47.2 35.68 180 top
R67  10K  [RES0402_0-5]  46.95 67.17 90 top
R68  10E_1%  [RES0402_0-5]  86.95 51.26 270 bottom
R69  10E_1%  [RES0402_0-5]  99.74 57.22 0 bottom
R70  10E_1%  [RES0402_0-5]  88.09 51.26 270 bottom
R71  10E_1%  [RES0402_0-5]  99.76 58.36 0 bottom
R72  220E  [RES0402_0-5]  50.58 77.4 0 top
R73  220E  [RES0402_0-5]  50.58 76.16 0 top
R74  0.01E_1%  [RES_FC4L16_0306-4_0-7]  102.6 57.81 270 bottom
R75  0.01E_1%  [RES_FC4L16_0306-4_0-7]  84.44 50.16 90 bottom
R76  0E  [RES0402_0-5]  56.26 79.09 0 top
R77  10K_1%  [RES0402_0-5]  101.85 83.89 270 top
R78  0E  [RES0402_0-5]  99.21 83.9 270 top
R79  4.7K  [RES0402_0-5]  101.53 85.88 0 top
R80  10K_1%  [RES0402_0-5]  100.47 83.9 90 top
R81  0E  [RES0201_0-5]  105.52 89.94 270 top
R82  0E  [RES0402_0-5]  58.11 30.57 270 bottom
R83  0E  [RES0402_0-5]  49.66 35.74 0 top
R84  4.7K  [RES0402_0-5]  43.32 55.11 180 top
R85  4.7K  [RES0402_0-5]  27.07 53.84 0 top
R86  10K  [RES0402_0-5]  41.16 52.57 180 top
R87  0E  [RES0402_0-5]  49.71 38.27 0 top
R89  100K  [RES0201_0-5]  29.33 55.21 180 top
R90  0E  [RES0402_0-5]  49.78 36.26 0 bottom
R91  0E  [RES0402_0-5]  49.78 37.4 0 bottom
R92  0E  [RES0402_0-5]  49.78 40.83 0 bottom
R93  0E  [RES0402_0-5]  49.78 35.12 0 bottom
R94  0E  [RES0402_0-5]  49.71 39.42 0 top
R95  0E  [RES0402_0-5]  49.71 41.7 0 top
R96  0E  [RES0402_0-5]  49.71 40.56 0 top
R97  0E  [RES0402_0-5]  49.71 42.84 0 top
R98  0E  [RES0402_0-5]  49.71 37.13 0 top
R99  0E  [RES0402_0-5]  49.69 33.85 0 bottom
R100  49.9K_1%  [RES0402_0-5]  32.59 48.12 270 bottom
R101  49.9K_1%  [RES0402_0-5]  36.57 43.62 180 bottom
R102  4.7K  [RES0402_0-5]  24.38 42.3 0 top
R103  49.9K_1%  [RES0402_0-5]  24.38 44.84 180 top
R104  49.9K_1%  [RES0402_0-5]  24.38 43.57 180 top
R105  49.9K_1%  [RES0402_0-5]  31.35 48.12 270 bottom
R106  49.9K_1%  [RES0402_0-5]  33.99 48.12 270 bottom
R107  49.9K_1%  [RES0402_0-5]  36.57 45.4 180 bottom
R108  10K  [RES0201_0-5]  27.16 40.66 180 top
R109  10K  [RES0402_0-5]  36.59 41.73 180 top
R110  100K  [RES0201_0-5]  36.33 40.37 0 top
R111  10K  [RES0201_0-5]  31.25 42.27 180 bottom
R112  22E_1%  [RES0201_0-5]  31.25 43.16 180 bottom
R113  1K_1%  [RES0402_0-5]  32.47 44.67 90 bottom
R114  0E  [RES0201_0-5]  31.25 44.18 180 bottom
R116  33E  [RES0402_0-5]  24.3 26.83 0 top
R117  0E  [RES0402_0-5]  49.78 39.69 0 bottom
R118  0E  [RES0402_0-5]  49.78 38.54 0 bottom
R119  10K  [RES0402_0-5]  47.31 36.13 180 bottom
R120  10K  [RES0402_0-5]  30.32 35.81 90 bottom
R121  10K  [RES0201_0-5]  35.68 36.89 270 bottom
R122  10K  [RES0402_0-5]  47.31 37.4 180 bottom
R123  22E_1%  [RES0402_0-5#2]  50.8 49.35 90 bottom
R124  10K  [RES0402_0-5]  43.96 48.73 90 bottom
R125  10K  [RES0402_0-5#2]  18.54 52.57 0 top
R126  0E  [RES0402_0-5#2]  18.54 51.3 180 top
R127  47K  [RES0402_0-5#2]  28.06 49.9 0 top
R128  47K  [RES0402_0-5#2]  28.82 47.99 0 top
R129  47K  [RES0402_0-5]  25.52 48.76 0 top
R130  47K  [RES0402_0-5]  25.52 50.03 0 top
R131  47K  [RES0402_0-5]  25.52 51.3 0 top
R132  10K  [RES0402_0-5]  28.19 51.17 0 top
R133  10K  [RES0402_0-5]  27.3 56.48 180 bottom
R134  10K  [RES0402_0-5]  52 49.28 270 bottom
R135  33E  [RES0402_0-5#2]  62.62 50.46 270 top
R136  33E  [RES0402_0-5]  63.91 50.39 270 bottom
R137  220E  [RES0402_0-5]  58.15 64.19 180 top
R138  220E  [RES0402_0-5]  56.7 56.31 180 top
R139  22E_1%  [RES0402_0-5#2]  61.41 50.46 270 top
R140  22E_1%  [RES0402_0-5]  60.2 50.39 270 top
R141  22E_1%  [RES0402_0-5]  62.69 50.39 270 bottom
R142  22E_1%  [RES0402_0-5]  109.84 53.12 180 bottom
R143  33E  [RES0402_0-5]  58.99 50.39 90 top
R144  22E_1%  [RES0402_0-5]  60.25 50.39 270 bottom
R145  33E  [RES0402_0-5]  58.99 50.39 90 bottom
R146  0E  [RES0402_0-5#2]  54.3 58.93 180 top
R147  0E  [RES0402_0-5]  48.42 57.26 180 top
R148  10K  [RES0402_0-5]  56.31 58.93 0 top
R149  10K  [RES0402_0-5]  48.91 55.68 270 top
R150  10K  [RES0402_0-5]  60.92 52.63 180 top
R151  10K  [RES0402_0-5]  61.47 50.39 90 bottom
R152  4.7K  [RES0402_0-5]  57.84 50.39 270 top
R153  4.7K  [RES0402_0-5]  56.7 50.39 270 top
R154  4.7K  [RES0402_0-5]  72.25 95.24 180 bottom
R155  4.7K  [RES0402_0-5]  72.25 96.43 180 bottom
R156  4.7K  [RES0402_0-5]  54.41 50.39 270 top
R157  4.7K  [RES0402_0-5]  55.55 50.39 270 top
R158  4.7K  [RES0402_0-5#2]  49.6 68.31 180 bottom
R159  4.7K  [RES0402_0-5]  49.53 69.71 180 bottom
R160  10K  [RES0402_0-5]  53.03 63.51 90 bottom
R161  10K  [RES0402_0-5#2]  43.68 65.27 0 bottom
R162  10K  [RES0402_0-5]  49.53 70.98 180 bottom
R163  0E  [RES0402_0-5]  44.19 63.51 90 bottom
R164  10K  [RES0402_0-5]  49.53 72.25 0 bottom
R165  10K  [RES0402_0-5#2]  39.37 70.98 180 bottom
R166  0E  [RES0402_0-5]  39.37 69.61 180 bottom
R167  10K  [RES0402_0-5#2]  111.33 94.47 270 bottom
R168  10K  [RES0402_0-5#2]  111.75 85.25 180 bottom
R169  10K  [RES0402_0-5]  109.57 85.25 0 bottom
R170  10K  [RES0402_0-5]  110.18 94.54 270 bottom
R171  59E_1%  [RES0402_0-5]  15.62 21.58 270 top
R172  0E  [RES0402_0-5#2]  20.19 20.05 180 top
R173  33E  [RES0402_0-5]  26.39 23.05 180 top
R174  59E_1%  [RES0402_0-5]  15.62 23.74 270 top
R175  10K  [RES0402_0-5#2]  17.27 18.28 0 bottom
R176  0E  [RES0402_0-5]  45.18 29.37 0 top
R177  22E_1%  [RES0402_0-5#2]  55.37 50.64 270 bottom
R178  0E  [RES0402_0-5#2]  50.43 31.62 0 top
R179  0E  [RES0402_0-5]  50.43 32.95 0 top
R180  10K  [RES0402_0-5]  29.49 62.43 0 top
R181  10K  [RES0402_0-5]  29.49 60.83 0 top
R182  10K  [RES0402_0-5]  41.23 58.95 180 top
R183  10K  [RES0402_0-5]  41.23 60.34 180 top
R184  1K_1%  [RES0402_0-5#2]  39.87 66.19 180 top
R185  0E  [RES0402_0-5]  53.91 50.54 270 bottom
R186  0E  [RES0402_0-5]  52.03 30.2 270 top
R187  10K  [RES0402_0-5]  52.89 33.76 270 bottom
R188  10K  [RES0402_0-5]  29.49 64.03 180 top
R189  4.7K  [RES0402_0-5]  41.23 61.49 0 top
R190  0E  [RES0402_0-5]  49.71 45.13 180 top
R191  0E  [RES0402_0-5]  49.77 42.07 180 bottom
R192  0E  [RES0402_0-5]  49.77 44.35 180 bottom
R193  0E  [RES0402_0-5]  49.77 45.5 180 bottom
R194  0E  [RES0402_0-5]  49.71 43.99 180 top
R195  0E  [RES0402_0-5]  49.71 47.42 180 top
R196  0E  [RES0402_0-5]  49.77 43.21 180 bottom
R197  33E  [RES0402_0-5]  50 87.68 180 bottom
R198  33E  [RES0402_0-5]  50 88.95 180 bottom
R199  33E  [RES0402_0-5]  31.21 72.89 0 bottom
R200  220E  [RES0402_0-5]  94.07 41.82 270 top
R201  10K  [RES0402_0-5]  54.34 30.53 90 bottom
R202  10K  [RES0402_0-5]  94.56 39.29 0 top
R203  2.49K_1%  [RES0402_0-5]  53.86 32.03 180 bottom
R204  10K  [RES0402_0-5]  26.54 29.07 270 bottom
R205  10K  [RES0402_0-5]  25.27 29.07 90 bottom
R206  10K  [RES0402_0-5]  36.83 29.83 0 bottom
R207  0E  [RES0402_0-5]  73.12 38.51 0 top
R208  0E  [RES0402_0-5]  73.12 34.7 0 top
R209  0E  [RES0402_0-5]  73.12 35.95 0 top
R210  0E  [RES0402_0-5]  83.18 66.15 0 bottom
R211  0E  [RES0402_0-5]  73.12 37.22 0 top
R212  0E  [RES0402_0-5]  83.18 69.96 0 bottom
R213  0E  [RES0402_0-5]  91.31 74.28 90 bottom
R214  2.2K  [RES0402_0-5]  90.07 76.77 270 bottom
R215  11K_1%  [RES0402_0-5]  94.25 62.44 180 bottom
R216  220E  [RES0402_0-5]  104.4 79.24 180 bottom
R217  10K  [RES0402_0-5]  80.3 37.24 0 top
R218  220E  [RES0402_0-5]  107.82 56.95 90 top
R219  220E  [RES0402_0-5]  107.82 57.06 90 bottom
R220  10K  [RES0402_0-5]  82.2 42.81 180 top
R221  0E  [RES0402_0-5]  105.27 84.48 180 bottom
R222  0E  [RES0402_0-5]  111.88 54.68 90 top
R223  0E  [RES0402_0-5]  113.02 58.11 90 bottom
R225  2.49K_1%  [RES0402_0-5]  83.38 69.84 0 top
R226  2.49K_1%  [RES0402_0-5]  83.38 70.98 0 top
R227  2.49K_1%  [RES0402_0-5]  93.85 74.28 270 bottom
R228  2.49K_1%  [RES0402_0-5]  92.34 77.04 180 bottom
R229  2.49K_1%  [RES0402_0-5]  94.59 77.89 90 bottom
R230  2.49K_1%  [RES0402_0-5]  83.38 74.41 180 top
R231  2.49K_1%  [RES0402_0-5]  83.38 72.13 180 top
R232  2.49K_1%  [RES0402_0-5]  83.38 73.27 180 top
R233  2.49K_1%  [RES0402_0-5]  86.93 62.42 180 bottom
R237  2.49K_1%  [RES0402_0-5]  85.97 69.84 0 top
R238  2.49K_1%  [RES0402_0-5]  85.97 70.98 0 top
R239  2.49K_1%  [RES0402_0-5]  92.58 74.28 90 bottom
R240  2.49K_1%  [RES0402_0-5]  92.34 75.9 0 bottom
R241  2.49K_1%  [RES0402_0-5]  91.8 78.33 0 bottom
R242  2.49K_1%  [RES0402_0-5]  85.97 74.66 0 top
R243  2.49K_1%  [RES0402_0-5]  85.97 72.12 180 top
R244  2.49K_1%  [RES0402_0-5]  85.97 73.27 180 top
R245  2.49K_1%  [RES0402_0-5]  86.93 63.67 180 bottom
R247  33E  [RES0402_0-5]  77.2 49.78 90 bottom
R248  33E  [RES0402_0-5]  76.86 49.78 90 top
R249  33E  [RES0402_0-5]  75.64 49.78 90 top
R250  33E  [RES0402_0-5]  75.73 49.78 90 bottom
R251  33E  [RES0402_0-5]  74.42 49.78 90 top
R252  33E  [RES0402_0-5]  70.85 49.78 90 bottom
R253  33E  [RES0402_0-5]  71.98 49.78 90 top
R254  33E  [RES0402_0-5]  74.43 49.78 90 bottom
R255  33E  [RES0402_0-5]  73.21 49.73 90 bottom
R256  33E  [RES0402_0-5]  73.2 49.78 90 top
R257  33E  [RES0402_0-5]  69.63 49.78 90 bottom
R258  33E  [RES0402_0-5]  69.54 49.78 90 top
R259  33E  [RES0402_0-5]  68.41 49.78 90 bottom
R260  33E  [RES0402_0-5]  70.76 49.78 90 top
R261  33E  [RES0402_0-5]  68.32 49.78 90 top
R262  33E  [RES0402_0-5]  67.19 49.78 90 bottom
R263  10K  [RES0201_0-5]  70.1 93.71 180 top
R264  10K  [RES0402_0-5]  69.99 92.68 0 top
R265  10K  [RES0402_0-5]  71.67 98.88 270 bottom
R266  10K  [RES0402_0-5]  77.26 101.76 270 bottom
R267  10K  [RES0402_0-5]  69.85 90.14 180 top
R271  0E  [RES0402_0-5]  16.72 36.99 0 top
R272  0E  [RES0402_0-5]  16.72 34.24 180 top
R273  0E  [RES0402_0-5]  17.21 38.55 270 top
R274  0E  [RES0402_0-5]  27.61 37.39 0 top
R275  0E  [RES0402_0-5]  39.73 30.5 270 top
R276  10K  [RES0402_0-5]  16.72 35.49 180 top
R277  10K  [RES0402_0-5]  26.43 67.3 0 bottom
R278  1K_1%  [RES0402_0-5]  14.97 70.75 0 top
R279  10K  [RES0402_0-5]  26.43 68.61 180 bottom
R280  10K  [RES0402_0-5]  37.04 68.47 0 bottom
R281  0E  [RES0402_0-5]  37.04 69.78 0 bottom
R282  10K  [RES0402_0-5]  25.68 64.29 180 top
R283  0E  [RES0402_0-5]  25.68 68.09 180 top
R284  0E  [RES0402_0-5]  25.68 63.08 180 top
R285  10K  [RES0402_0-5]  25.68 65.56 0 top
R286  4.7K  [RES0402_0-5]  63.56 77.71 180 top
R287  4.7K  [RES0402_0-5]  65.21 79.09 180 top
R288  10K  [RES0402_0-5]  62.35 96.76 270 bottom
R289  10K  [RES0402_0-5]  61.21 96.76 270 bottom
R290  10K  [RES0402_0-5]  60.07 96.76 270 bottom
R291  10K  [RES0402_0-5]  58.92 96.76 270 bottom
R292  10K  [RES0402_0-5]  57.78 96.76 270 bottom
R293  10K  [RES0402_0-5]  56.64 96.76 270 bottom
R295  0E  [RES0201_0-5]  55.88 99.56 90 bottom
R296  0E  [RES0201_0-5]  56.88 99.56 90 bottom
R297  0E  [RES0201_0-5]  57.85 99.56 90 bottom
R298  0E  [RES0201_0-5]  58.84 99.56 90 bottom
R299  0E  [RES0201_0-5]  60.07 99.56 90 bottom
R300  0E  [RES0201_0-5]  61.08 99.56 90 bottom
R301  0E  [RES0201_0-5]  62.1 99.56 90 bottom
R302  0E  [RES0201_0-5]  63.11 99.56 90 bottom
R303  0E  [RES0201_0-5]  64.13 99.56 90 bottom
R304  0E  [RES0201_0-5]  65.15 99.56 90 bottom
R305  0E  [RES0201_0-5]  66.16 99.56 90 bottom
R306  0E  [RES0201_0-5]  38.22 77.2 180 top
R307  0E  [RES0201_0-5]  45.08 74.94 0 bottom
R308  4.7K  [RES0402_0-5]  40.02 75.04 0 top
R309  4.7K  [RES0402_0-5]  40.02 77.2 0 top
R310  0E  [RES0201_0-5]  45.08 77.46 0 bottom
R311  0E  [RES0201_0-5]  45.08 76.26 0 bottom
R312  0E  [RES0201_0-5]  40.18 78.27 180 top
R313  0E  [RES0201_0-5]  40.18 76.06 180 top
R314  0E  [RES0201_0-5]  45.09 78.48 0 bottom
R315  0E  [RES0201_0-5]  40.18 79.36 180 top
R316  10K  [RES0402_0-5]  54.1 84.71 0 top
R317  10K  [RES0402_0-5]  54.1 85.98 0 top
R318  10K  [RES0402_0-5]  54.1 87.24 0 top
R319  10K  [RES0402_0-5]  54.1 88.52 0 top
R320  10K  [RES0402_0-5]  61.48 77.71 180 top
R321  10K  [RES0402_0-5]  64.66 81.27 270 top
R322  10K  [RES0402_0-5]  63.37 83.3 270 bottom
R323  22K  [RES0402_0-5]  66.46 84.71 180 top
R324  22K  [RES0402_0-5]  66.46 85.98 180 top
R325  22K  [RES0402_0-5]  66.46 87.25 180 top
R326  22K  [RES0402_0-5]  66.46 88.52 180 top
R327  49.9E_1%  [RES0402_0-5]  58.67 92.18 0 bottom
R328  0E  [RES0402_0-5#2]  64.38 92.82 180 bottom
R329  0E  [RES0402_0-5#2]  69.18 92.7 90 bottom
R330  10K  [RES0402_0-5]  67.99 92.7 270 bottom
R331  1K_1%  [RES0402_0-5]  69.59 106.93 90 top
R332  51K  [RES0402_0-5]  19.49 104.76 180 top
R333  30K  [RES0402_0-5#2]  17.59 104.76 180 top
R334  51E  [RES0402_0-5]  34.03 86.22 180 top
R335  0E  [RES0805_0-75]  11.68 88.25 270 bottom
R336  33E  [RES0402_0-5]  39.18 100.8 180 bottom
R337  10K  [RES0402_0-5]  39.18 99.56 0 bottom
R338  0E  [RES0402_0-5]  22.47 84.32 270 bottom
R339  100E  [RES0402_0-5]  19.93 84.32 270 bottom
R340  330K_1%  [RES0402_0-5]  21.85 104.87 0 bottom
R341  220K_1%  [RES0402_0-5]  21.85 106.15 180 bottom
R342  220E  [RES0402_0-5]  23.49 100.19 90 top
R343  180E  [RES0402_0-5]  22.6 103.11 180 top
R344  33E  [RES0402_0-5]  50.41 94.98 180 bottom
R345  1K_1%  [RES0402_0-5]  39.18 89 0 bottom
R346  1K_1%  [RES0402_0-5]  39.18 87.8 0 bottom
R347  1K_1%  [RES0402_0-5]  39.18 84.22 0 bottom
R348  1K_1%  [RES0402_0-5]  37.31 84.76 270 bottom
R349  1K_1%  [RES0402_0-5]  39.18 90.19 180 bottom
R350  1K_1%  [RES0402_0-5]  39.18 86.61 180 bottom
R351  1K_1%  [RES0402_0-5]  39.18 85.41 180 bottom
R352  1K_1%  [RES0402_0-5]  36.12 84.76 90 bottom
R353  10K  [RES0402_0-5]  34.16 82.16 90 bottom
R354  4.7K  [RES0402_0-5]  26.03 100.67 180 top
R355  10K  [RES0402_0-5]  35.43 82.16 270 bottom
R356  10K  [RES0402_0-5]  39.18 97.09 180 bottom
R357  10K  [RES0402_0-5]  39.18 98.32 180 bottom
R358  4.87K_1%  [RES0402_0-5]  39.18 91.38 0 bottom
R359  4.7K  [RES0201_0-5]  40.13 81.24 0 bottom
R360  4.7K  [RES0201_0-5]  40.13 82.51 0 bottom
R361  0E  [RES0201_0-5]  49.78 82.51 0 bottom
R362  0E  [RES0201_0-5]  49.78 81.24 0 bottom
R365  10K  [RES0201_0-5]  31.24 105.26 0 top
R366  10K  [RES0201_0-5]  31.24 103.99 0 top
R367  10K  [RES0201_0-5]  31.24 102.72 0 top
R368  10K  [RES0201_0-5]  31.24 101.45 0 top
R369  10K  [RES0201_0-5]  31.24 100.18 0 top
R370  10K  [RES0201_0-5]  31.24 98.91 0 top
R371  0E  [RES0201_0-5]  44.54 105.27 0 top
R372  0E  [RES0201_0-5]  44.54 104.13 0 top
R373  0E  [RES0201_0-5]  44.54 102.73 0 top
R374  0E  [RES0201_0-5]  44.54 101.59 0 top
R375  0E  [RES0201_0-5]  44.54 100.19 0 top
R376  0E  [RES0201_0-5]  44.54 98.92 0 top
R377  10K  [RES0201_0-5]  18.51 81.47 270 bottom
R378  0E  [RES0201_0-5]  18.84 72.56 0 bottom
R381  220E  [RES0402_0-5]  73.15 75.3 0 top
R382  220E  [RES0402_0-5]  73.15 73.27 0 top
R383  220E  [RES0402_0-5]  73.15 71.23 0 top
R384  220E  [RES0402_0-5]  73.15 69.2 0 top
R385  220E  [RES0402_0-5]  61.34 69.2 180 top
R386  220E  [RES0402_0-5]  61.34 71.23 180 top
R387  220E  [RES0402_0-5]  61.34 73.27 180 top
R388  220E  [RES0402_0-5]  61.34 75.3 180 top
R389  10K  [RES0402_0-5]  62.35 68.69 0 bottom
R390  10K  [RES0402_0-5]  62.35 69.96 0 bottom
R391  10K  [RES0402_0-5]  71.88 69.2 90 bottom
R392  10K  [RES0402_0-5]  52.15 74.96 90 bottom
R393  10K  [RES0402_0-5]  53.42 74.96 270 bottom
R394  0E  [RES0402_0-5]  55.96 74.96 270 bottom
R395  10K  [RES0402_0-5]  59.29 74.56 90 bottom
R396  1K_1%  [RES0402_0-5]  59.78 30.57 270 top
R397  1K_1%  [RES0402_0-5]  59.3 30.57 270 bottom
R398  1K_1%  [RES0402_0-5]  56.92 30.57 270 bottom
R399  1K_1%  [RES0402_0-5]  55.24 30.57 270 top
R400  1K_1%  [RES0402_0-5]  55.72 30.57 270 bottom
R401  0E  [RES0402_0-5]  32.89 18.8 90 top
R402  0E  [RES0402_0-5]  25.52 19.78 270 top
R403  0E  [RES0402_0-5]  58.42 28.37 90 top
R404  0E  [RES0402_0-5]  61.48 30.11 270 top
R405  10K  [RES0402_0-5]  59.87 27.63 90 bottom
R406  10K  [RES0402_0-5]  56.52 21.07 0 bottom
R407  10K  [RES0402_0-5]  56.64 9.39 270 top
R408  10K  [RES0402_0-5]  57.5 19.67 0 top
R409  10K  [RES0402_0-5]  52.46 21.07 180 bottom
R410  10K  [RES0402_0-5]  51.55 10.02 0 top
R411  10K  [RES0402_0-5]  52.39 19.42 0 top
R412  0E  [RES0402_0-5]  64.06 22.38 270 bottom
R413  0E  [RES0402_0-5]  65.45 22.38 270 bottom
R414  10K  [RES0402_0-5]  64.91 27.66 90 bottom
R415  10K  [RES0402_0-5]  52.94 27.66 90 bottom
R416  0E  [RES0402_0-5]  32.89 7.61 180 top
R417  9.1K_1%  [RES0402_0-5]  34.79 7.61 0 top
R418  11K_1%  [RES0402_0-5]  42.67 27.28 270 top
R419  0E  [RES0402_0-5]  67.93 10.77 270 top
R420  0E  [RES0402_0-5]  71.05 16.73 270 top
R421  0E  [RES0402_0-5]  64.17 54.24 0 bottom
R422  0E  [RES0402_0-5]  63.82 50.39 270 top
R423  0E  [RES0402_0-5]  68.45 16.53 270 top
R425  10K  [RES0402_0-5]  52.7 106.92 270 top
R426  10K  [RES0402_0-5]  59.69 106.92 270 top
R427  10K  [RES0402_0-5]  52.41 96.32 0 bottom
R428  10K  [RES0402_0-5]  53.63 89.94 180 bottom
R429  10K  [RES0402_0-5]  66.67 106.92 270 top
R430  10K_1%  [RES0402_0-5]  92.99 54.17 90 bottom
R431  10K  [RES0402_0-5]  83.56 35.37 180 top
R432  0E  [RES0402_0-5]  83.56 36.61 180 top
R433  4.7K_1%  [RES0402_0-5]  79.2 29.48 90 top
R434  10K  [RES0402_0-5]  80.44 29.48 270 top
R435  0E  [RES0402_0-5]  107.57 27.8 270 bottom
R436  2.2K  [RES0402_0-5]  74.9 32.65 180 bottom
R437  2.2K  [RES0402_0-5]  72.94 32.65 0 bottom
R439  22E  [RES0402_0-5]  29.44 57.46 180 top
R440  22E  [RES0402_0-5]  41.16 53.84 0 top
R441  22E  [RES0402_0-5]  41.16 55.11 0 top
R442  22E  [RES0402_0-5]  29.19 53.84 180 top
R451  22E  [RES0402_0-5]  32.6 48.14 90 top
R452  22E  [RES0402_0-5]  36.59 43.62 0 top
R453  22E  [RES0402_0-5]  27.54 42.3 180 top
R454  22E  [RES0402_0-5]  27.54 44.84 180 top
R455  22E  [RES0402_0-5]  27.54 43.57 180 top
R456  22E  [RES0402_0-5]  31.33 48.14 90 top
R457  22E  [RES0402_0-5]  33.85 48.14 90 top
R458  22E  [RES0402_0-5]  36.59 45.41 0 top
R461  10K  [RES0402_0-5]  53.84 64.34 0 top
R463  3.16K_1%  [RES0402_0-5]  86.5 44.92 0 top
R464  1.5K_0.1%  [RES0402_0-5]  87.48 43.65 0 top
R465  10K_1%  [RES0402_0-5]  91.96 44.85 0 top
R466  10K  [RES0402_0-5]  17.06 21.14 90 top
R467  0E  [RES0402_0-5]  50.52 34.63 180 top
R468  10K  [RES0402_0-5]  55.41 96.76 270 bottom
R469  1K_1%  [RES0402_0-5]  89.36 31.89 180 bottom
R470  2.2K  [RES0402_0-5]  76.14 28.89 90 top
R471  2.2K  [RES0402_0-5]  72.23 27.88 180 top
R472  2.2K  [RES0402_0-5]  78.2 29.43 270 bottom
R473  2.2K  [RES0402_0-5]  69.66 27.49 0 bottom
R474  10K  [RES0402_0-5]  75.65 31.36 180 bottom
R475  10K  [RES0402_0-5]  69.5 29.83 0 bottom
R476  0E  [RES0201_0-5]  83.44 82.11 180 top
R477  0E  [RES0201_0-5]  83.44 81.12 180 top
R479  0E  [RES0201_0-5]  83.79 79.76 270 top
R480  0E  [RES0201_0-5]  84.4 78.27 180 top
R481  0E  [RES0201_0-5]  98.74 94.93 0 top
R482  0E  [RES0201_0-5]  98.74 93.94 0 top
R483  0E  [RES0201_0-5]  98.74 92.95 0 top
R484  0E  [RES0201_0-5]  98.74 91.96 0 top
R485  0E  [RES0201_0-5]  83.44 82.11 180 bottom
R486  0E  [RES0201_0-5]  83.44 81.12 180 bottom
R487  0E  [RES0201_0-5]  83.79 79.76 270 bottom
R488  0E  [RES0201_0-5]  84.4 78.27 0 bottom
R489  0E  [RES0201_0-5]  98.74 94.93 0 bottom
R490  0E  [RES0201_0-5]  98.74 93.94 0 bottom
R491  0E  [RES0201_0-5]  98.74 92.95 0 bottom
R492  0E  [RES0201_0-5]  98.74 91.96 0 bottom
R493  0E  [RES0201_0-5]  98.65 96.93 0 top
R494  0E  [RES0201_0-5]  98.65 97.92 0 top
R495  0E  [RES0201_0-5]  98.65 99.9 0 top
R496  0E  [RES0201_0-5]  98.65 98.91 0 top
R497  0E  [RES0201_0-5]  99.42 103.03 0 top
R498  0E  [RES0201_0-5]  99.42 104.02 0 top
R499  0E  [RES0201_0-5]  99.42 105.01 0 top
R500  0E  [RES0201_0-5]  99.42 106 0 top
R501  0E  [RES0201_0-5]  98.65 96.93 0 bottom
R502  0E  [RES0201_0-5]  98.65 97.92 0 bottom
R503  0E  [RES0201_0-5]  98.65 99.9 0 bottom
R504  0E  [RES0201_0-5]  98.65 98.91 0 bottom
R505  0E  [RES0201_0-5]  99.42 103.03 0 bottom
R506  0E  [RES0201_0-5]  99.42 104.02 0 bottom
R507  0E  [RES0201_0-5]  99.42 105.01 0 bottom
R508  0E  [RES0201_0-5]  99.42 106 0 bottom
R509  0E  [RES0201_0-5]  71.42 83.78 90 top
R510  0E  [RES0201_0-5]  70.43 83.78 90 top
R511  0E  [RES0201_0-5]  69.44 83.78 90 top
R512  0E  [RES0201_0-5]  68.45 83.78 90 top
R513  0E  [RES0201_0-5]  76.53 74.65 180 top
R514  0E  [RES0201_0-5]  76.54 75.68 180 top
R515  0E  [RES0201_0-5]  76.54 76.57 180 top
R516  0E  [RES0201_0-5]  77.28 77.67 180 top
R517  0E  [RES0201_0-5]  71.42 83.78 90 bottom
R518  0E  [RES0201_0-5]  70.43 83.78 90 bottom
R519  0E  [RES0201_0-5]  69.44 83.78 90 bottom
R520  0E  [RES0201_0-5]  68.45 83.78 90 bottom
R521  0E  [RES0201_0-5]  76.53 74.65 180 bottom
R522  0E  [RES0201_0-5]  76.54 75.68 180 bottom
R523  0E  [RES0201_0-5]  76.54 76.67 180 bottom
R524  0E  [RES0201_0-5]  77.28 77.67 180 bottom
R525  0E  [RES0201_0-5]  77.27 73.63 0 bottom
R526  0E  [RES0201_0-5]  77.27 72.64 0 bottom
R527  0E  [RES0201_0-5]  77.27 71.65 0 bottom
R528  0E  [RES0201_0-5]  77.27 70.66 0 bottom
R529  0E  [RES0201_0-5]  76.55 69.67 180 top
R530  0E  [RES0201_0-5]  76.55 68.68 180 top
R531  0E  [RES0201_0-5]  76.55 67.69 180 top
R532  0E  [RES0201_0-5]  76.55 66.7 180 top
R533  0E  [RES0201_0-5]  77.25 73.64 0 top
R534  0E  [RES0201_0-5]  77.27 72.64 0 top
R535  0E  [RES0201_0-5]  77.27 71.65 0 top
R536  0E  [RES0201_0-5]  77.27 70.66 0 top
R537  0E  [RES0201_0-5]  76.55 69.67 180 bottom
R538  0E  [RES0201_0-5]  76.55 68.68 180 bottom
R539  0E  [RES0201_0-5]  76.55 67.69 180 bottom
R540  0E  [RES0201_0-5]  76.55 66.7 180 bottom
R1381  10K  [RES0402_0-5]  80.86 60.34 90 bottom
R1383  10K  [RES0402_0-5]  47.8 81.55 180 top
R1399  0E  [RES0402_0-5]  87.56 107.46 180 bottom
R1647  4.7K  [RES0402_0-5]  24.33 25.62 180 top
R1648  0E  [RES0402_0-5]  37.43 16.58 0 top
R1649  0E  [RES0402_0-5]  65.4 28.2 90 top
R1652  33E  [RES0402_0-5]  66.43 50.41 90 top
R1653  33E  [RES0402_0-5]  65.2 50.39 90 top
R1667  49.9K_1%  [RES0402_0-5]  27.3 57.46 180 top
R1668  49.9K_1%  [RES0402_0-5]  43.32 53.84 0 top
